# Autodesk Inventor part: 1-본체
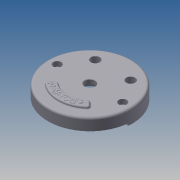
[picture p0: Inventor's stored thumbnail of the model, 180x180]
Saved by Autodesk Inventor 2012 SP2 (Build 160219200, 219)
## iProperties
Created: 2015-04
Part Number: 1-본체
Material: 알루미늄-6061
Document SubType Name: Modeling
Designer: Administrator
Density: 2.71 g/cm^3
Mass: 1043.31 g
Surface Area: 1023.34 cm^2
Volume: 384.984 cm^3
Author: Administrator
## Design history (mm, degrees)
sketch "스케치1"
  geometry: C1 r 95 at (0, 0); 1 further point
  constraints: 1 centre point, 1 coincident
  dimensions: "d0" = 190 diameter of C1
extrude "돌출1" new body sketch "스케치1" distance "d1" = 32; taper "d2" = 0 deg
sketch "스케치4"
  geometry: C1 r 95 at (0, 0) reference; C2 r 90 at (0, 0)
  constraints: 1 centre point, 1 coincident
  dimensions: "d14" = 180 diameter of C2
extrude "돌출3" cut sketch "스케치4" distance "d15" = 18; taper "d16" = 0 deg
sketch "스케치5"
  geometry: L1 (-95, 0)-(95, 0); L2 (0, 0)-(-89.658, -7.844); L3 (0, 0)-(89.658, -7.844); L4 (89.658, -7.844)-(94.638, -8.28); L5 (-89.658, -7.844)-(-94.638, -8.28); A1 r 90 centre (0, 0) between (89.658, -7.844) and (-89.658, -7.844) reference; A2 r 95 centre (0, 0) between (-95, 0) and (95, 0) reference
  constraints: 10 end point, 6 point on circle, 2 collinear, 1 coincident, 1 horizontal, 1 midpoint
  dimensions: "d17" = 5 deg angle of L3 L1; "d18" = 5 deg angle of L2 L1
extrude "돌출4" cut sketch "스케치5" distance "d19" = 5; taper "d20" = 0 deg
sketch "스케치6"
  geometry: L1 (-89.196, 12)-(-76.916, 12); L2 (40.249, 12)-(47.117, 12); L3 (-76.916, 12)-(-47.117, 12); L4 (-47.117, 12)-(-40.249, 12); L5 (47.117, 12)-(76.916, 12); L6 (76.916, 12)-(89.196, 12); A1 r 90 centre (0, 0) between (-89.196, 12) and (89.196, 12) reference; A2 r 42 centre (0, 0) between (-38.056, 17.769) and (38.056, 17.769); A3 r 10 centre (-76.916, 22) between (-86.53, 24.75) and (-76.916, 12); A4 r 10 centre (-47.117, 22) between (-47.117, 12) and (-38.056, 17.769); A5 r 10 centre (47.117, 22) between (38.056, 17.769) and (47.117, 12); A6 r 10 centre (76.916, 22) between (76.916, 12) and (86.53, 24.75); A7 r 90 centre (0, 0) between (89.658, -7.844) and (-89.658, -7.844) reference; A8 r 10 centre (-76.916, 22) between (-76.916, 12) and (-86.53, 24.75); A9 r 10 centre (-47.117, 22) between (-38.056, 17.769) and (-47.117, 12); A10 r 10 centre (47.117, 22) between (47.117, 12) and (38.056, 17.769); A11 r 10 centre (76.916, 22) between (86.53, 24.75) and (76.916, 12); A12 r 42 centre (0, 0) between (38.056, 17.769) and (-38.056, 17.769); 4 further points
  constraints: 26 point on circle, 16 tangent, 12 end point, 10 centre point, 6 horizontal, 4 midpoint, 2 point on line, 1 coincident, 1 horizontal alignment
  dimensions: "d21" = 84 diameter of A2; "d23" = 20 diameter of A3; "d24" = 20 diameter of A4; "d25" = 20 diameter of A5; "d26" = 20 diameter of A6; "d29" = 12 vertical distance of point (-62.016, 12) A1.centre
extrude "돌출5" cut sketch "스케치6" distance "d30" = 7; taper "d31" = 0 deg
sketch "스케치7"
  geometry: C1 r 35 at (0, 0); A1 r 42 centre (0, 0) between (38.056, 17.769) and (-38.056, 17.769) reference
  constraints: 1 centre point, 1 coincident
  dimensions: "d32" = 70 diameter of C1
extrude "돌출6" join sketch "스케치7" distance "d33" = 10; taper "d34" = -10 deg
sketch "스케치8"
  geometry: L1 (47.117, 12)-(76.916, 12) reference; L2 (0, 95)-(0, 0); C1 r 15 at (-40, 52); C2 r 15 at (40, 52); A1 r 42 centre (0, 0) between (38.056, 17.769) and (-38.056, 17.769) reference
  constraints: 2 centre point, 2 end point, 1 horizontal alignment, 1 perpendicular, 1 symmetric about line, 1 vertical alignment, 1 other
  dimensions: "d35" = 30 diameter of C1; "d36" = 30 diameter of C2; "d37" = 52 vertical distance of A1.centre C2.centre; "d38" = 80 distance of C2.centre C1.centre
extrude "돌출7" join sketch "스케치8" distance "d39" = 25; taper "d40" = 0 deg
sketch "스케치9"
  geometry: L1 (-47.117, 12)-(-76.916, 12) reference; L2 (0, 0)-(0, -95); C1 r 35 at (0, 0) reference; C2 r 9 at (-74, 0); C3 r 9 at (74, 0)
  constraints: 2 centre point, 2 end point, 2 horizontal alignment, 1 perpendicular, 1 symmetric about line, 1 vertical alignment, 1 other
  dimensions: "d41" = 18 diameter of C2; "d42" = 18 diameter of C3; "d43" = 148 distance of C3.centre C2.centre
extrude "돌출8" join sketch "스케치9" distance "d44" = 18; taper "d45" = 0 deg
sketch "스케치10"
  geometry: L1 (-47.117, 12)-(-76.916, 12) reference; L2 (0, 0)-(90, 0); L3 (0, 0)-(0, -95); C1 r 35 at (0, 0) reference; A1 r 90 centre (0, 0) between (-86.53, 24.75) and (86.53, 24.75) reference; A2 r 59 centre (0, -19) between (0, -78) and (58.704, -13.1); A3 r 41 centre (0, -19) between (0, -60) and (40.794, -14.9); A4 r 9 centre (-49.749, -14) between (-40.794, -14.9) and (-58.704, -13.1); A5 r 9 centre (49.749, -14) between (58.704, -13.1) and (40.794, -14.9); A6 r 59 centre (0, -19) between (-58.704, -13.1) and (0, -78); A7 r 59 centre (0, -19) between (58.704, -13.1) and (-58.704, -13.1); A8 r 41 centre (0, -19) between (-40.794, -14.9) and (0, -60); A9 r 41 centre (0, -19) between (40.794, -14.9) and (-40.794, -14.9); A10 r 9 centre (-49.749, -14) between (-58.704, -13.1) and (-40.794, -14.9); A11 r 9 centre (49.749, -14) between (40.794, -14.9) and (58.704, -13.1); 1 further point
  constraints: 21 point on circle, 10 centre point, 4 end point, 3 point on line, 2 tangent, 1 coincident, 1 horizontal alignment, 1 parallel, 1 perpendicular, 1 vertical alignment, 1 other
  dimensions: "d46" = 118 diameter of A2; "d47" = 82 diameter of A3; "d48" = 19 distance of A2.centre C1.centre; "d49" = 18 diameter of A4; "d50" = 18 diameter of A5; "d51" = 5 vertical distance of A5.centre A2.centre
extrude "돌출9" cut sketch "스케치10" distance "d52" = 7; taper "d53" = 0 deg
hole "구멍1" diameter "d56" = 20; stored, may be unused: countersink angle "d60" = 90 deg, drill point angle "d62" = 118 deg; dims "d54" = 10, "d55" = 10, "d57" = 6, "d58" = 4, "d59" = 2, "d61" = 8
hole "구멍2" diameter "d65" = 20; stored, may be unused: countersink angle "d69" = 90 deg, drill point angle "d71" = 118 deg; dims "d63" = 10, "d64" = 10, "d66" = 6, "d67" = 4, "d68" = 2, "d70" = 8
sketch "스케치11"
  geometry: C1 r 9 at (-74, 0) reference; C2 r 9 at (74, 0) reference; 2 further points
  constraints: 2 coincident
hole "구멍3" sketch "스케치11" at (-74, 0), (74, 0) diameter "d72" = 11; stored, may be unused: countersink angle "d76" = 90 deg, drill point angle "d78" = 118 deg; dims "d73" = 6, "d74" = 18, "d75" = 11, "d77" = 8
hole "구멍4" diameter "d81" = 50; stored, may be unused: countersink angle "d85" = 90 deg, drill point angle "d87" = 0 deg; dims "d79" = 10, "d80" = 10, "d82" = 6, "d83" = 4, "d84" = 2, "d86" = 15
hole "구멍5" diameter "d90" = 23; stored, may be unused: countersink angle "d94" = 90 deg, drill point angle "d96" = 0 deg; dims "d88" = 10, "d89" = 10, "d91" = 6, "d92" = 4, "d93" = 2, "d95" = 15
sketch "스케치12"
  geometry: L1 (0, 0)-(-36.062, -36.062); L2 (0, 0)-(36.062, -36.062); L3 (-39.44, -39.44)-(-47.244, -47.244); L4 (39.44, -39.44)-(47.244, -47.244); C1 r 11.5 at (0, 0) reference; A1 r 51 centre (0, 0) between (-32.699, -39.138) and (32.699, -39.138); A2 r 72 centre (0, 0) between (-46.97, -54.569) and (46.97, -54.569); A3 r 5 centre (-43.709, -50.78) between (-47.244, -47.244) and (-46.97, -54.569); A4 r 5 centre (-35.904, -42.975) between (-32.699, -39.138) and (-39.44, -39.44); A5 r 5 centre (35.904, -42.975) between (39.44, -39.44) and (32.699, -39.138); A6 r 5 centre (43.709, -50.78) between (46.97, -54.569) and (47.244, -47.244); 2 further points
  constraints: 16 point on circle, 8 end point, 8 tangent, 6 centre point, 4 point on line, 3 equal radius, 2 coincident, 2 collinear, 1 horizontal alignment
  dimensions: "d97" = 102 diameter of A1; "d99" = 90 deg angle of L2 L1; "d100" = 72 radius of A2; "d101" = 5 radius of A3
extrude "돌출10" join sketch "스케치12" distance "d102" = 5; taper "d103" = 0 deg
sketch "스케치13"
  geometry: C1 r 68 at (0, 0); A1 r 72 centre (0, 0) between (-46.97, -54.569) and (46.97, -54.569) reference
  constraints: 1 centre point, 1 coincident, 1 other
  dimensions: "d104" = 136 diameter of C1
feature "엠보싱1" sketch "스케치13" dims "d2" = 0, "d105" = 0.5, "d106" = 0
sketch "스케치14"
  geometry: L1 (-6, 13.748)-(-6, -13.748); L2 (6, 13.748)-(6, -13.748); L3 (66.252, 6)-(93.748, 6); L4 (66.252, -6)-(93.748, -6); L5 (0, 0)-(0, -15); L6 (80, 0)-(95, 0); C1 r 10 at (80, 0) reference; A1 r 15 centre (0, 0) between (-6, 13.748) and (-6, -13.748) reference; A2 r 15 centre (80, 0) between (66.252, 6) and (93.748, 6) reference; 1 further point
  constraints: 12 end point, 10 point on circle, 4 perpendicular, 1 horizontal, 1 vertical, 2 other
  dimensions: "d107" = 12 distance between parallel lines of L2 L1; "d108" = 12 distance between parallel lines of L4 L3
extrude "돌출11" cut sketch "스케치14" distance "d109" = 3; taper "d110" = 0 deg
fillet "모깎기1" dims "d111" = 3
fillet "모깎기2" dims "d112" = 2
fillet "모깎기3" dims "d113" = 5
fillet "모깎기4" dims "d114" = 0.3
fillet "모깎기5" dims "d115" = 3
chamfer "모따기1" distance "d116" = 1; stored, may be unused: second distance "d117" = 2, angle "d118" = 45 deg
fillet "모깎기6" dims "d119" = 3
fillet "모깎기7" dims "d120" = 1
chamfer "모따기2" distance "d121" = 1; stored, may be unused: second distance "d122" = 2, angle "d123" = 45 deg
node "솔리드1"
node "투영된 루프3"
other parameters: "d8" = 12, "d98" = 144
